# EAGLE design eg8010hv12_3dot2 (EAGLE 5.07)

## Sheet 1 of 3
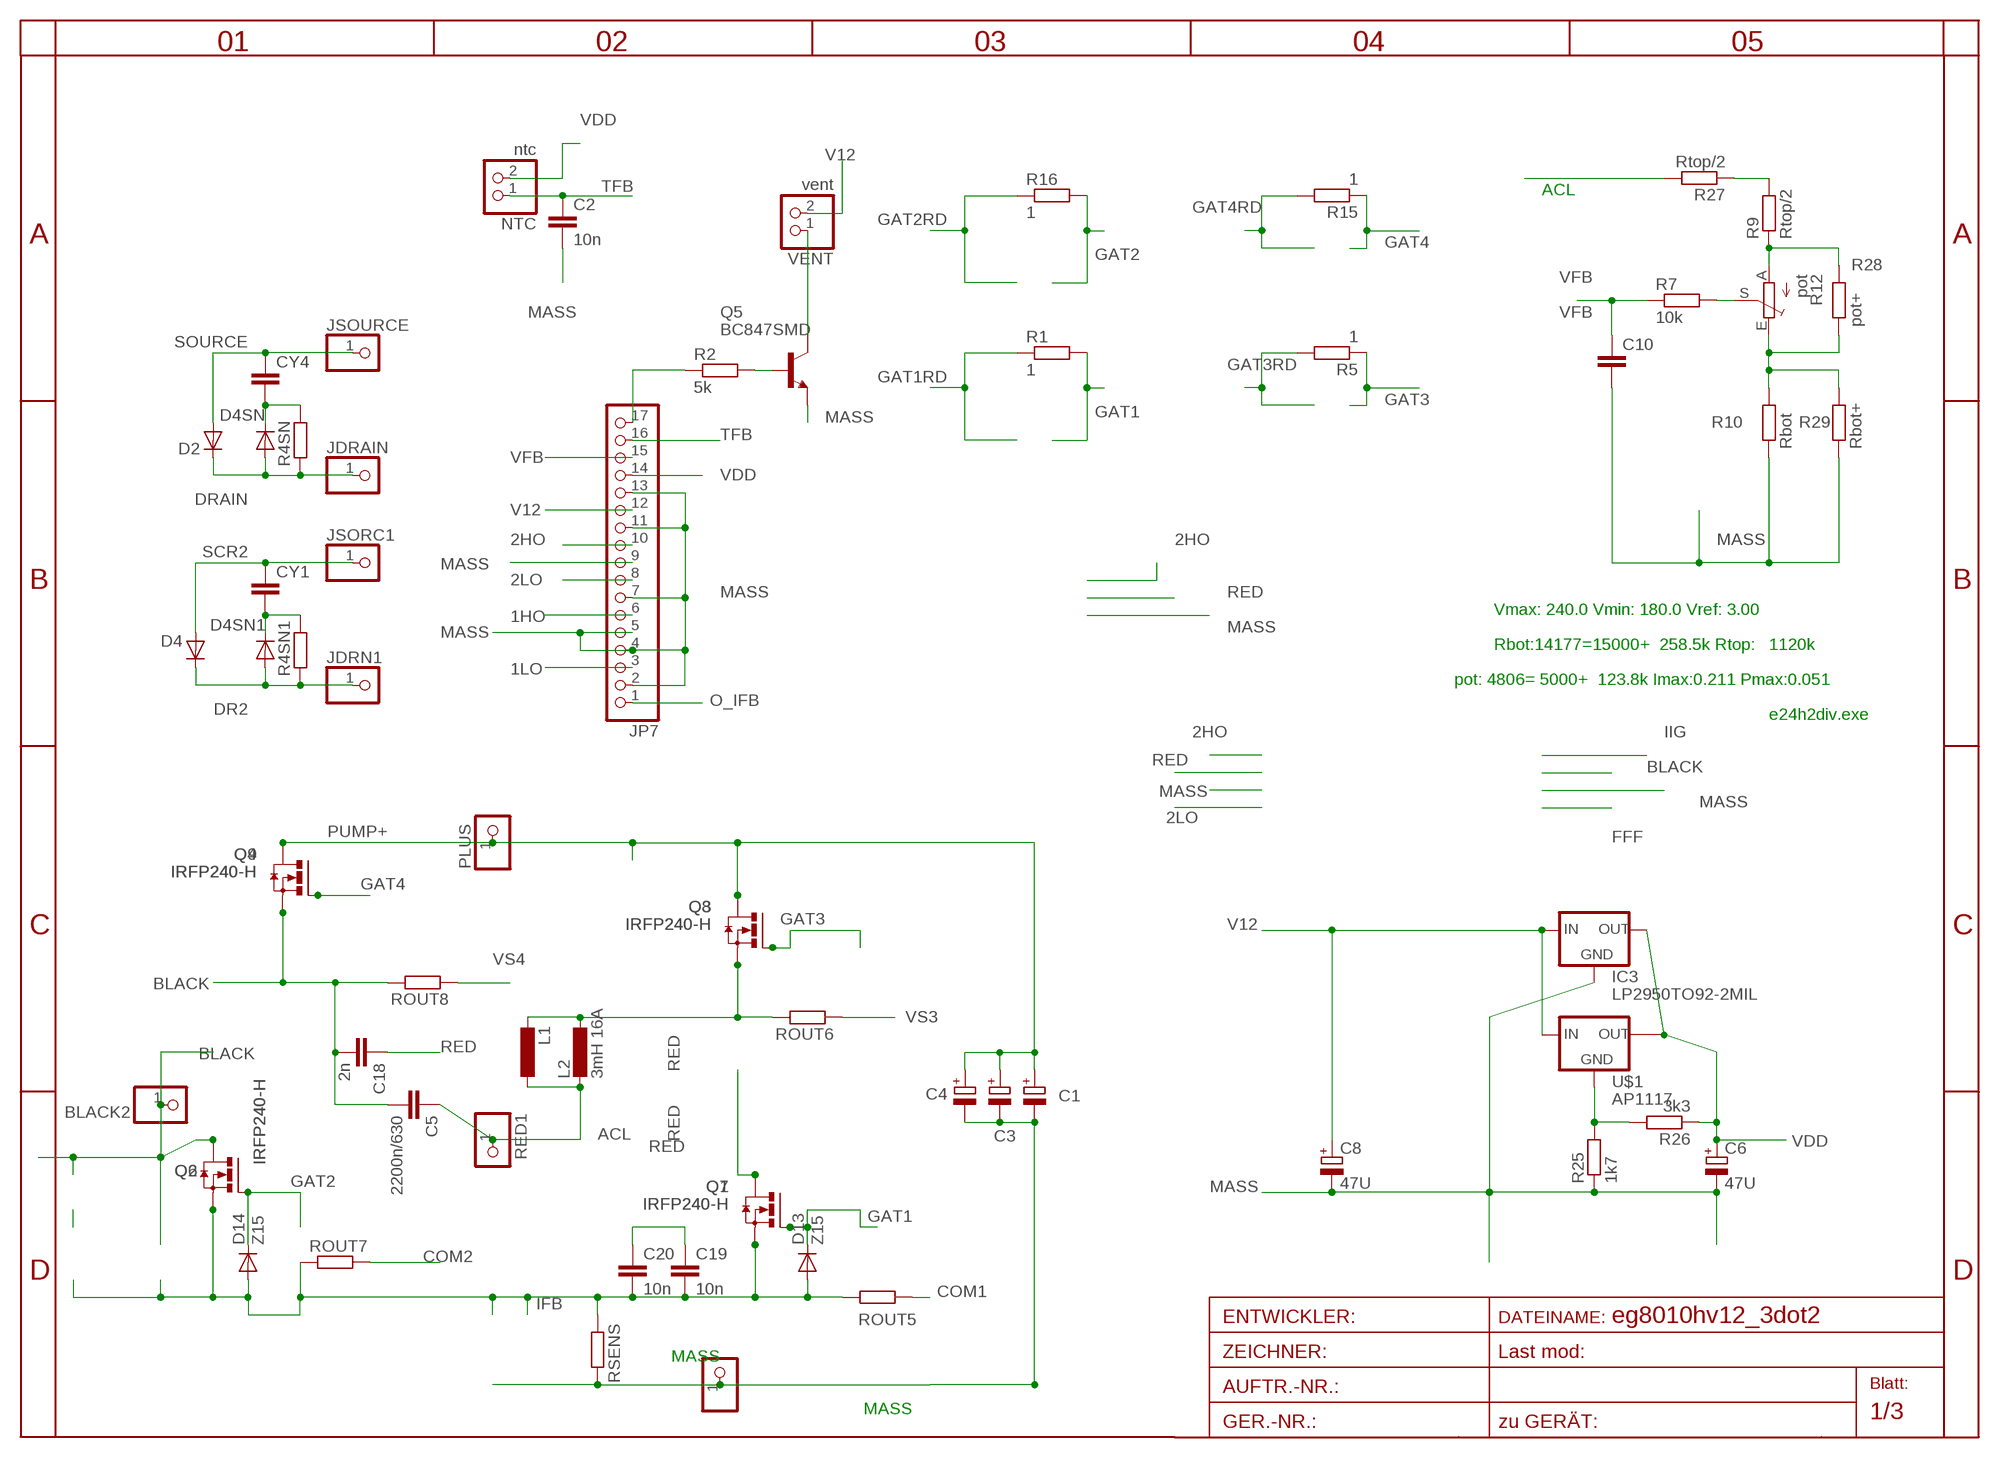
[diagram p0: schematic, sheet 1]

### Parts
BLACK2  PINHD-1X12MM3  [1X2MM3]
C1  CPOL-EUE5-13  [E5-13]
C2  10n  C-EUC0805  [C0805]
C3  CPOL-EUE5-13  [E5-13]
C4  CPOL-EUE5-13  [E5-13]
C5  2200n/630  C-EU275-173X316  [C275-173X316]
C6  47U  CPOL-EUSMCA  [SMC_A]
C8  47U  CPOL-EUSMCA  [SMC_A]
C10  C-EUC0805  [C0805]
C18  2n  C-EU050-024X044  [C050-024X044]
C19  10n  C-EU050-024X044  [C050-024X044]
C20  10n  C-EU050-024X044  [C050-024X044]
CY1  CXXC10B5  [XC10B5]
CY4  CXXC10B5  [XC10B5]
D2  DIODE-SMC  [SMC]
D4  DIODE-SMC  [SMC]
D4SN  DIODE-P1-10  [P1-10]
D4SN1  DIODE-P1-10  [P1-10]
D13  Z15  DIODE-MINIMELF  [MINIMELF]
D14  Z15  DIODE-MINIMELF  [MINIMELF]
IC3  LP2950TO92-2MIL  [TO92-2MIL]
JDRAIN  PINHD-1X11MM0  [1X1MM0]
JDRN1  PINHD-1X11MM0  [1X1MM0]
JP7  PINHD-1X17  [1X17]
JSORC1  PINHD-1X11MM0  [1X1MM0]
JSOURCE  PINHD-1X11MM0  [1X1MM0]
L1  L-EU4.13  [0204/13]
L2  3mH 16A  L-EURNG  [RING]
MINUS  PINHD-1X12MM3  [1X2MM3]
NTC  ntc  PINHD-1X2STR  [1X02]
PLUS  PINHD-1X12MM3  [1X2MM3]
Q1  IRFP240-H  [TO247BH]
Q2  IRFP240-H  [TO247BH]
Q3  IRFP240-H  [TO247BH]
Q4  IRFP240-H  [TO247BH]
Q5  BC847SMD  [SOT23]
Q6  IRFP240-H  [TO247BH]
Q7  IRFP240-H  [TO247BH]
Q8  IRFP240-H  [TO247BH]
Q9  IRFP240-H  [TO247BH]
R1  1  R-EU_R2512  [R2512]
R2  5k  R-EU_R0805  [R0805]
R4SN  R-EU_0207/10  [0207/10]
R4SN1  R-EU_0207/10  [0207/10]
R5  1  R-EU_R2512  [R2512]
R7  10k  R-EU_R0805  [R0805]
R9  Rtop/2  R-EU_R1206  [R1206]
R10  Rbot  R-EU_R0805  [R0805]
R12  pot  TRIM_EU-B64Y  [B64Y]
R15  1  R-EU_R2512  [R2512]
R16  1  R-EU_R2512  [R2512]
R25  1k7  R-EU_R0805  [R0805]
R26  3k3  R-EU_R0805  [R0805]
R27  Rtop/2  R-EU_R1206  [R1206]
R28  pot+  R-EU_R1206  [R1206]
R29  Rbot+  R-EU_R0805  [R0805]
RED1  PINHD-1X12MM3  [1X2MM3]
ROUT5  R-EU_R2512  [R2512]
ROUT6  R-EU_R2512  [R2512]
ROUT7  R-EU_R2512  [R2512]
ROUT8  R-EU_R2512  [R2512]
RSENS  R-EU_WIRE  [WIRE]
U$1  AP1117  [SOT223]
VENT  vent  PINHD-1X2STR  [1X02]

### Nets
1HO: JP7.6 ; also sheet 3
1LO: JP7.3 ; also sheet 3
2HO: JP7.10 ; also sheet 3
2LO: JP7.8 ; also sheet 3
ACL: C5.1 L1.1 L2.2 R27.2 RED1.1
BLACK: BLACK2.1 C5.2 C18.2 Q2.D Q4.S Q6.D Q9.S ROUT8.2
COM1: ROUT5.1 ; also sheet 3
COM2: ROUT7.2 ; also sheet 3
DR2: D4.C D4SN1.A JDRN1.1 R4SN1.1
DRAIN: D2.C D4SN.A JDRAIN.1 R4SN.1
GAT1: D13.C Q1.G Q7.G R1.2
GAT1RD: R1.1 ; also sheet 3
GAT2: D14.C Q2.G Q6.G R16.2
GAT2RD: R16.1 ; also sheet 3
GAT3: Q3.G Q8.G R5.1
GAT3RD: R5.2 ; also sheet 3
GAT4: Q4.G Q9.G R15.1
GAT4RD: R15.2 ; also sheet 3
IFB: C19.2 C20.2 D13.A D14.A Q1.S Q2.S Q6.S Q7.S ROUT5.2 ROUT7.1 RSENS.1 ; also sheet 3
MASS: C1.- C2.2 C3.- C4.- C6.- C8.- C10.2 IC3.2(GND) JP7.2 JP7.4 JP7.5 JP7.7 JP7.9 JP7.11 JP7.13 MINUS.1 Q5.2(E) R10.1 R25.1 R29.1 RSENS.2 ; also sheet 2,3
N$1: Q5.3(C) VENT.1
N$2: Q5.1(B) R2.2
N$3: JP7.17 R2.1
N$17: R25.2 R26.2 U$1.1(GND)
N$23: R9.2 R27.1
N$29: R10.2 R12.E R28.1 R29.2
N$30: R9.1 R12.A R28.2
N$31: R7.2 R12.S
O_IFB: JP7.1 ; also sheet 3
PUMP+: C1.+ C3.+ C4.+ C19.1 C20.1 PLUS.1 Q3.D Q4.D Q8.D Q9.D ; also sheet 2
RED: C18.1 L1.2 L2.1 Q1.D Q3.S Q7.D Q8.S ROUT6.2
SCR2: CY1.1 D4.A JSORC1.1
SNUB1: CY1.2 D4SN1.C R4SN1.2
SNUB2: CY4.2 D4SN.C R4SN.2
SOURCE: CY4.1 D2.A JSOURCE.1
TFB: C2.1 JP7.16 NTC.1
V12: C8.+ IC3.3(IN) JP7.12 U$1.3(IN) VENT.2 ; also sheet 2,3
VDD: C6.+ IC3.1(OUT) JP7.14 NTC.2 R26.1 U$1.4(TAB)
VFB: C10.1 JP7.15 R7.1
VS3: ROUT6.1 ; also sheet 3
VS4: ROUT8.1 ; also sheet 3
Unconnected: U$1.2(OUT)

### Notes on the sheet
- Vmax: 240.0 Vmin: 180.0 Vref: 3.00
- Rbot:14177=15000+  258.5k Rtop:   1120k
- pot: 4806= 5000+  123.8k Imax:0.211 Pmax:0.051
- e24h2div.exe

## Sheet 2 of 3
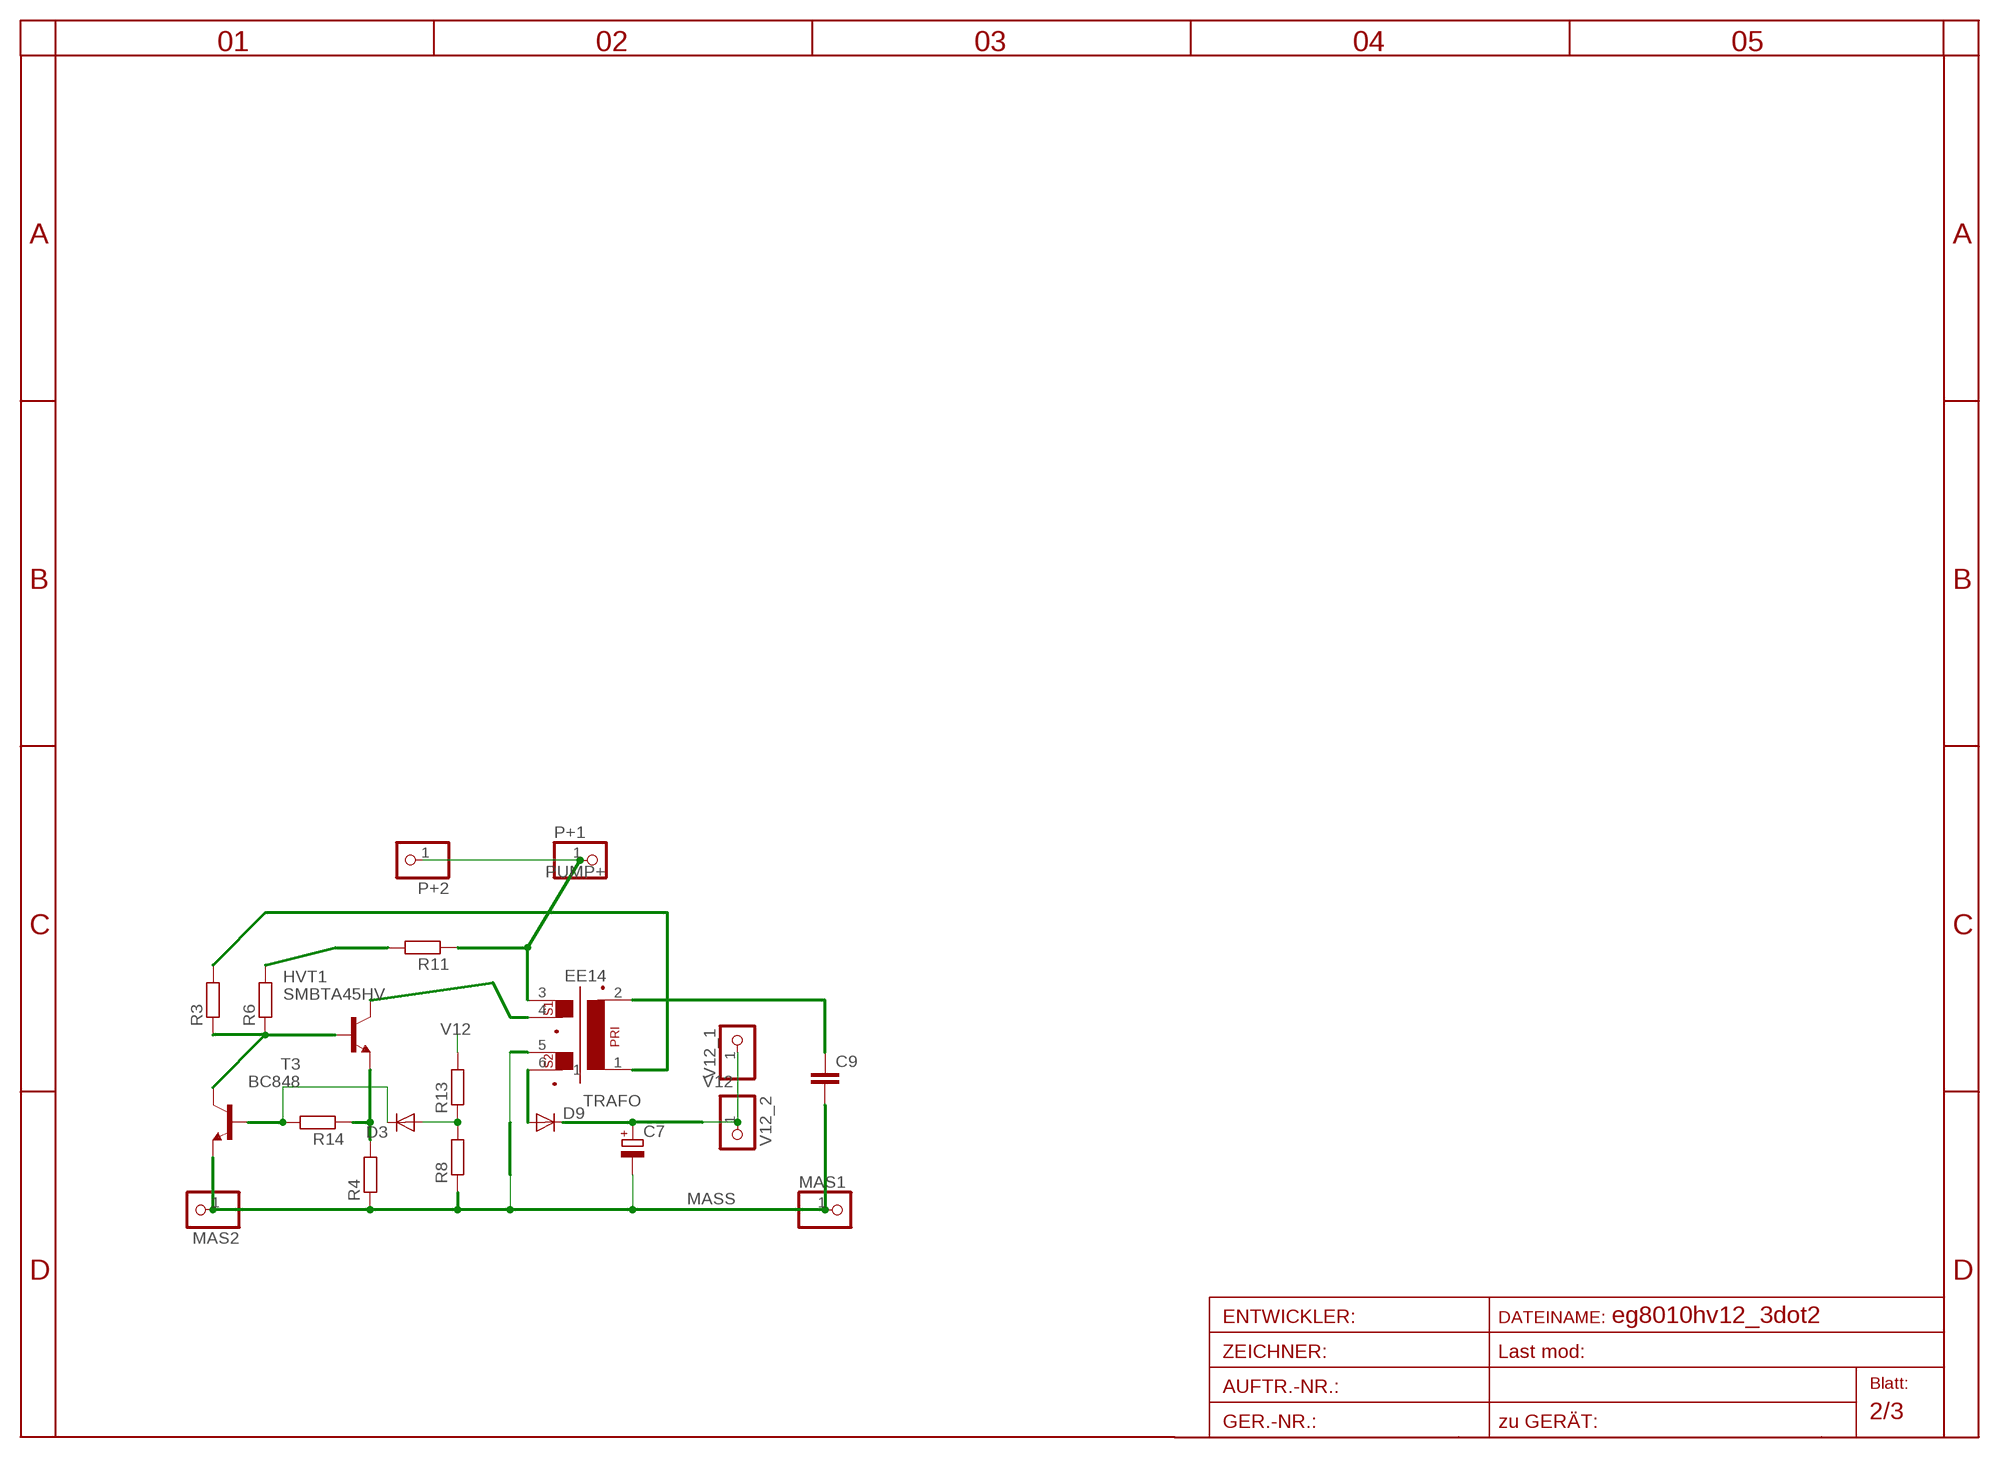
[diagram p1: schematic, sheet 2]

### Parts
C7  CPOL-EUSMCA  [SMC_A]
C9  C-EUC0805  [C0805]
D3  DIODE-MINIMELF  [MINIMELF]
D9  DIODE-SMA-DO214  [SMA-DO214AC]
HVT1  SMBTA45HV  [SOT23HV]
MAS1  PINHD-1X11X0.4  [1X01]
MAS2  PINHD-1X11X0.4  [1X01]
P+1  PINHD-1X11X0.4  [1X01]
P+2  PINHD-1X11X0.4  [1X01]
R3  R-EU_R0805  [R0805]
R4  R-EU_R0805  [R0805]
R6  R-EU_R1206  [R1206]
R8  R-EU_R0805  [R0805]
R11  R-EU_R1206  [R1206]
R13  R-EU_R0805  [R0805]
R14  R-EU_R0805  [R0805]
T3  BC848  [SOT23]
TRAFO  EE14  [EE14]
V12_1  PINHD-1X11X0.4  [1X01]
V12_2  PINHD-1X11X0.4  [1X01]

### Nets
A: D9.A TRAFO.6
B1C2: HVT1.1(B) R3.1 R6.1 T3.C
BT1: D3.C R14.2 T3.B
C1: HVT1.3(C) TRAFO.4
EB: HVT1.2(E) R4.2 R14.1
MASS: C7.- C9.2 MAS1.1 MAS2.1 R4.1 R8.1 T3.E TRAFO.5 ; also sheet 1,3
N$6: R3.2 TRAFO.1
N$7: C9.1 TRAFO.2
N$8: R6.2 R11.2
N$10: D3.A R8.2 R13.1
PUMP+: P+1.1 P+2.1 R11.1 TRAFO.3 ; also sheet 1
V12: C7.+ D9.K(C) R13.2 V12_1.1 V12_2.1 ; also sheet 1,3

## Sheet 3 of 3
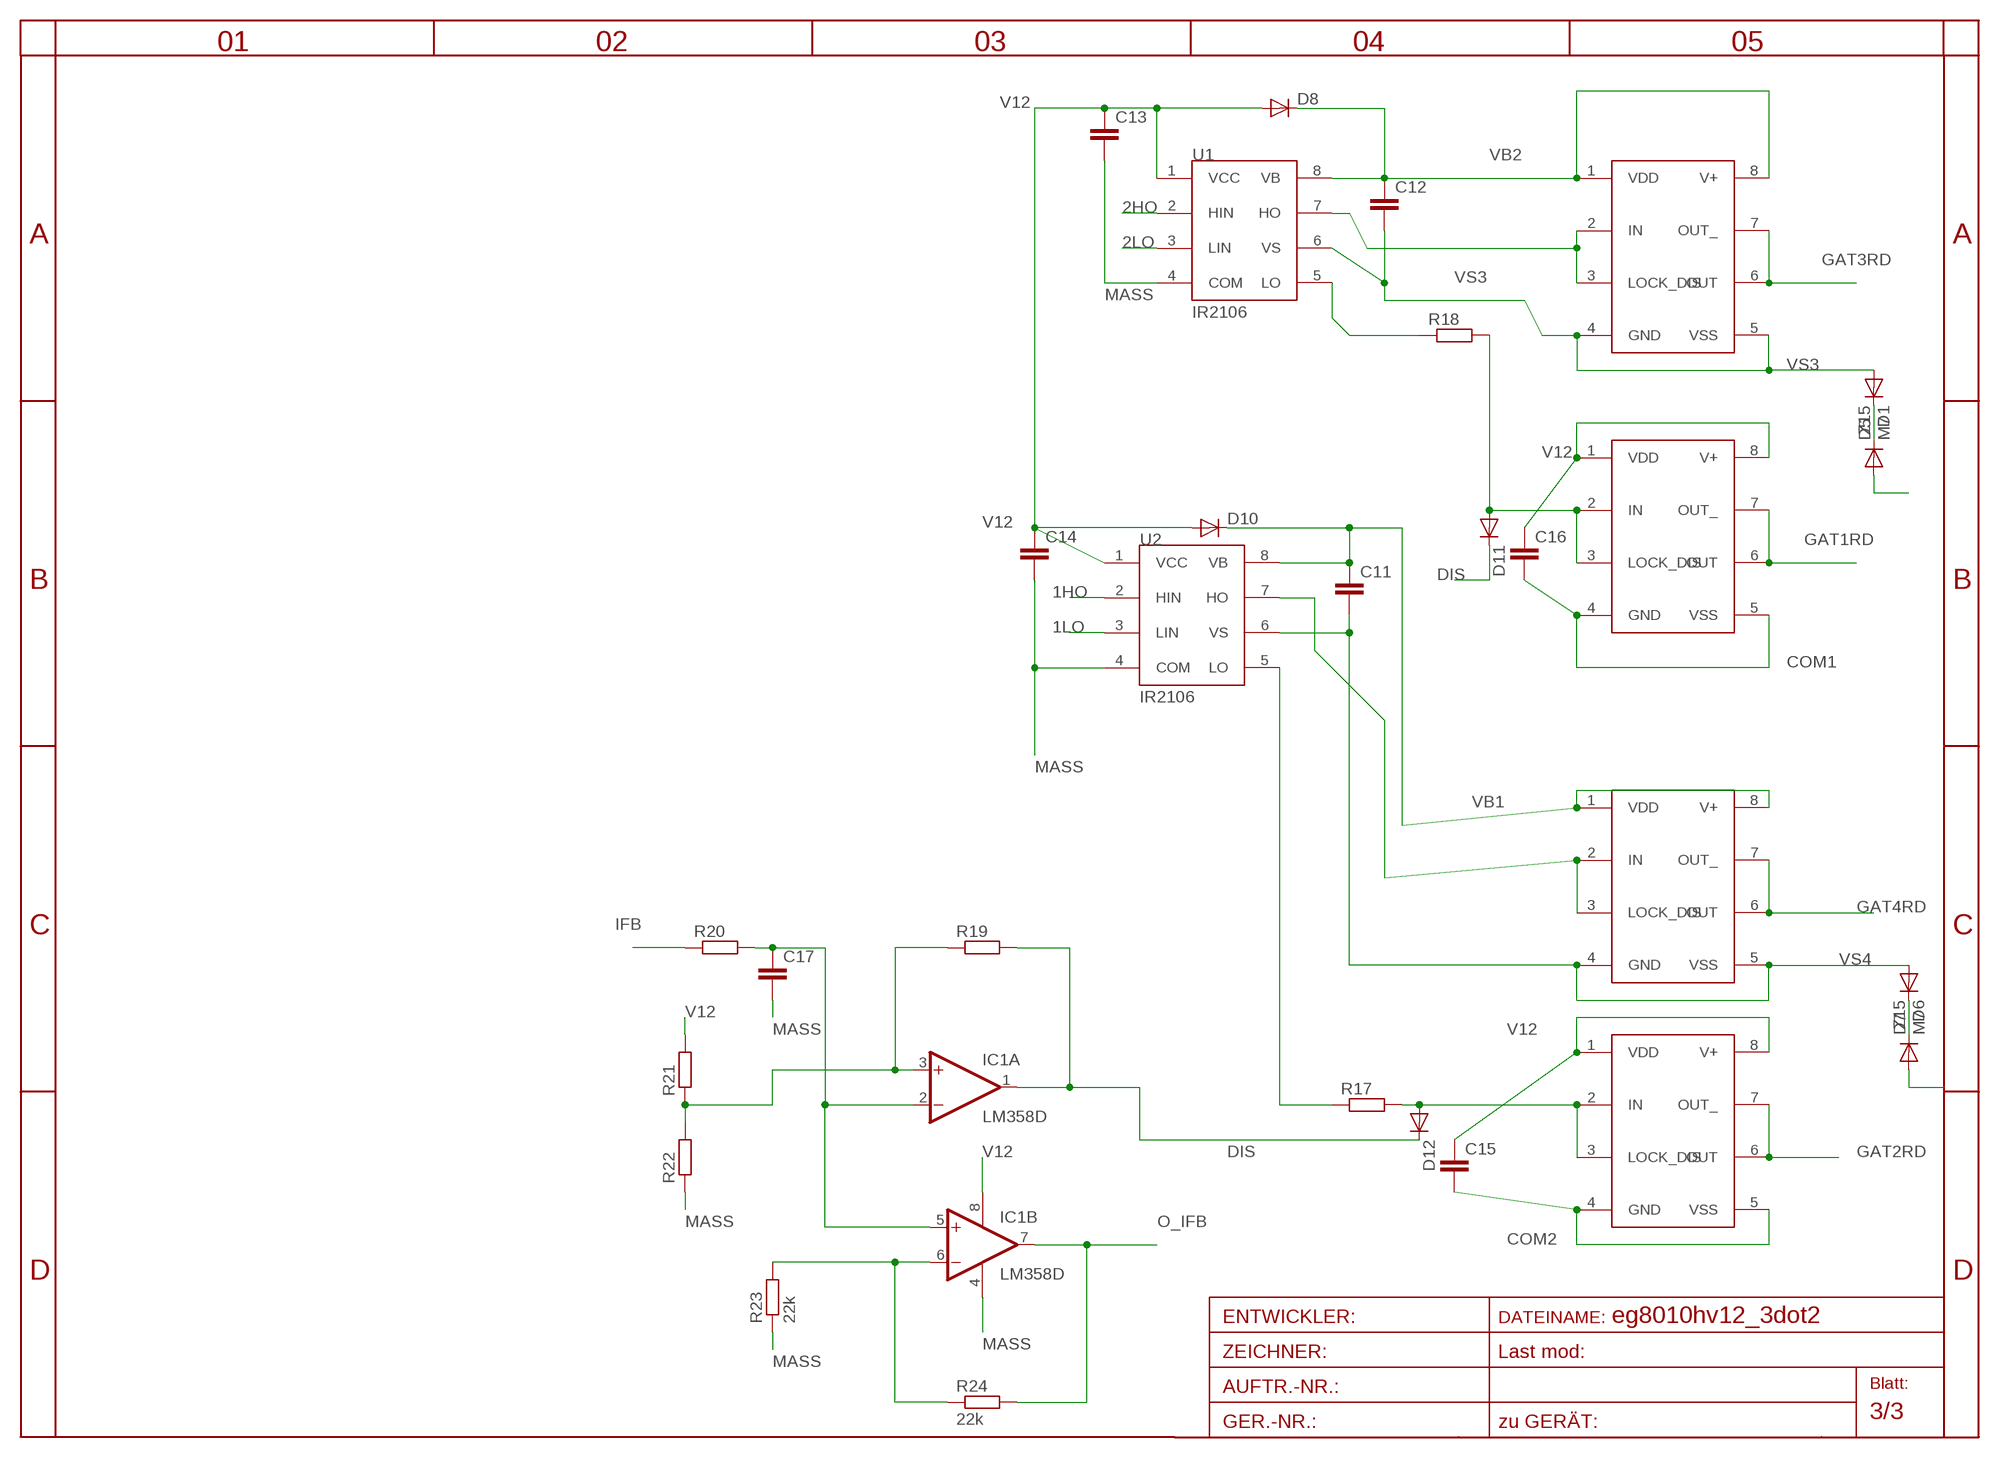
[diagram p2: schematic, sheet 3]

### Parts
1HDRV  TC4432X  [SO-08]
1LODRV  TC4432X  [SO-08]
2HDRV  TC4432X  [SO-08]
2LODRV  TC4432X  [SO-08]
C11  C-EUC058MLCC  [C058-020X040]
C12  C-EUC058MLCC  [C058-020X040]
C13  C-EUC1206  [C1206]
C14  C-EUC0805  [C0805]
C15  C-EUC1206  [C1206]
C16  C-EUC1206  [C1206]
C17  C-EUC1206  [C1206]
D1  Z15  DIODE-MINIMELF  [MINIMELF]
D5  M7  DIODE-SMA-DO214  [SMA-DO214AC]
D6  Z15  DIODE-MINIMELF  [MINIMELF]
D7  M7  DIODE-SMA-DO214  [SMA-DO214AC]
D8  DIODE-SMA-DO214  [SMA-DO214AC]
D10  DIODE-SMA-DO214  [SMA-DO214AC]
D11  DIODE-MINIMELF  [MINIMELF]
D12  DIODE-MINIMELF  [MINIMELF]
IC1  LM358D  [SO08]
R17  R-EU_0207-17  [0207/17]
R18  R-EU_0204/5  [0204/5]
R19  R-EU_R1206  [R1206]
R20  R-EU_R0805  [R0805]
R21  R-EU_R0805  [R0805]
R22  R-EU_R0805  [R0805]
R23  22k  R-EU_R0805  [R0805]
R24  22k  R-EU_R0805  [R0805]
U1  IR2106  [SO8-5]
U2  IR2106  [SO8-5]

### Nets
1HO: U2.2(HIN) ; also sheet 1
1LO: U2.3(LIN) ; also sheet 1
2HO: U1.2(HIN) ; also sheet 1
2LO: U1.3(LIN) ; also sheet 1
COM1: 2LODRV.4(GND) 2LODRV.5(VSS) C16.2 ; also sheet 1
COM2: 1LODRV.4(GND) 1LODRV.5(VSS) C15.2 ; also sheet 1
DIS: D11.C D12.C IC1.1(A:OUT) R19.2
GAT1RD: 2LODRV.6(OUT) 2LODRV.7(OUT_) ; also sheet 1
GAT2RD: 1LODRV.6(OUT) 1LODRV.7(OUT_) ; also sheet 1
GAT3RD: 2HDRV.6(OUT) 2HDRV.7(OUT_) ; also sheet 1
GAT4RD: 1HDRV.6(OUT) 1HDRV.7(OUT_) ; also sheet 1
IFB: R20.1 ; also sheet 1
MASS: C13.2 C14.2 C17.2 D5.A D7.A IC1.4(P:V-) R22.1 R23.1 U1.4(COM) U2.4(COM) ; also sheet 1,2
N$4: R18.1 U1.5(LO)
N$5: 1LODRV.2(IN) 1LODRV.3(LOCK_DIS) D12.A R17.2
N$9: IC1.3(A:+IN) R19.1 R21.1 R22.2
N$11: R17.1 U2.5(LO)
N$12: 2HDRV.2(IN) 2HDRV.3(LOCK_DIS) U1.7(HO)
N$13: 1HDRV.2(IN) 1HDRV.3(LOCK_DIS) U2.7(HO)
N$15: C17.1 IC1.2(A:-IN) IC1.5(B:+IN) R20.2
N$16: 2LODRV.2(IN) 2LODRV.3(LOCK_DIS) D11.A R18.2
N$18: IC1.6(B:-IN) R23.2 R24.1
N$20: D1.C D5.K(C)
N$24: D6.C D7.K(C)
O_IFB: IC1.7(B:OUT) R24.2 ; also sheet 1
V12: 1LODRV.1(VDD) 1LODRV.8(V+) 2LODRV.1(VDD) 2LODRV.8(V+) C13.1 C14.1 C15.1 C16.1 D8.A D10.A IC1.8(P:V+) R21.2 U1.1(VCC) U2.1(VCC) ; also sheet 1,2
VB1: 1HDRV.1(VDD) 1HDRV.8(V+) C11.1 D10.K(C) U2.8(VB)
VB2: 2HDRV.1(VDD) 2HDRV.8(V+) C12.1 D8.K(C) U1.8(VB)
VS3: 2HDRV.4(GND) 2HDRV.5(VSS) C12.2 D1.A U1.6(VS) ; also sheet 1
VS4: 1HDRV.4(GND) 1HDRV.5(VSS) C11.2 D6.A U2.6(VS) ; also sheet 1

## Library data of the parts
1HDRV 1LODRV 2HDRV 2LODRV = microchip:TC4432
BLACK2 JDRAIN JDRN1 JSORC1 JSOURCE MAS1 MAS2 MINUS P+1 P+2 PLUS RED1 V12_1 V12_2 = pinhead:PINHD-1X1: PIN HEADER
C1 C3 C4 C6-C8 = rcl:CPOL-EU: POLARIZED CAPACITOR, European symbol
C2 C5 C9-C20 = rcl:C-EU: CAPACITOR, European symbol
CY1 CY4 = rcl:CX: X CAPACITOR
D1-D4 D4SN D4SN1 D5-D14 = diode:DIODE-: DIODE
HVT1 = transistor-npn:SMBTA45
IC1 = linear:LM358: OP AMP also LM158; LM258; LM2904 Source: http://cache.national.com/ds/LM/LM158.pdf
IC3 = v-reg:LP2950?*: Source: http://cache.national.com/ds/LP/LP2950.pdf
JP7 = pinhead:PINHD-1X17: PIN HEADER
L1 L2 = rcl:L-EU: INDUCTOR, European symbol
NTC VENT = pinhead:PINHD-1X2: PIN HEADER
Q1-Q4 Q6-Q9 = transistor-power:IRFP240: HEXFET Power MosFet Source: http://www.irf.com/
Q5 = transistor-npn:BC847*: NPN Transistor
R1-R4 R4SN R4SN1 R5 R6 R8 R11 R13-R24 ROUT5-ROUT8 RSENS = rcl:R-EU_: RESISTOR, European symbol
R7 R9 R10 R25-R29 = rcl-2:R-EU_: RESISTOR, European symbol
R12 = pot:TRIM_EU-: POTENTIOMETER
T3 = transistor:BC848: NPN TRANSISTOR
TRAFO = trafo:EE14
U1 U2 = irf-2:IR2106
U$1 = v-reg:AP1117

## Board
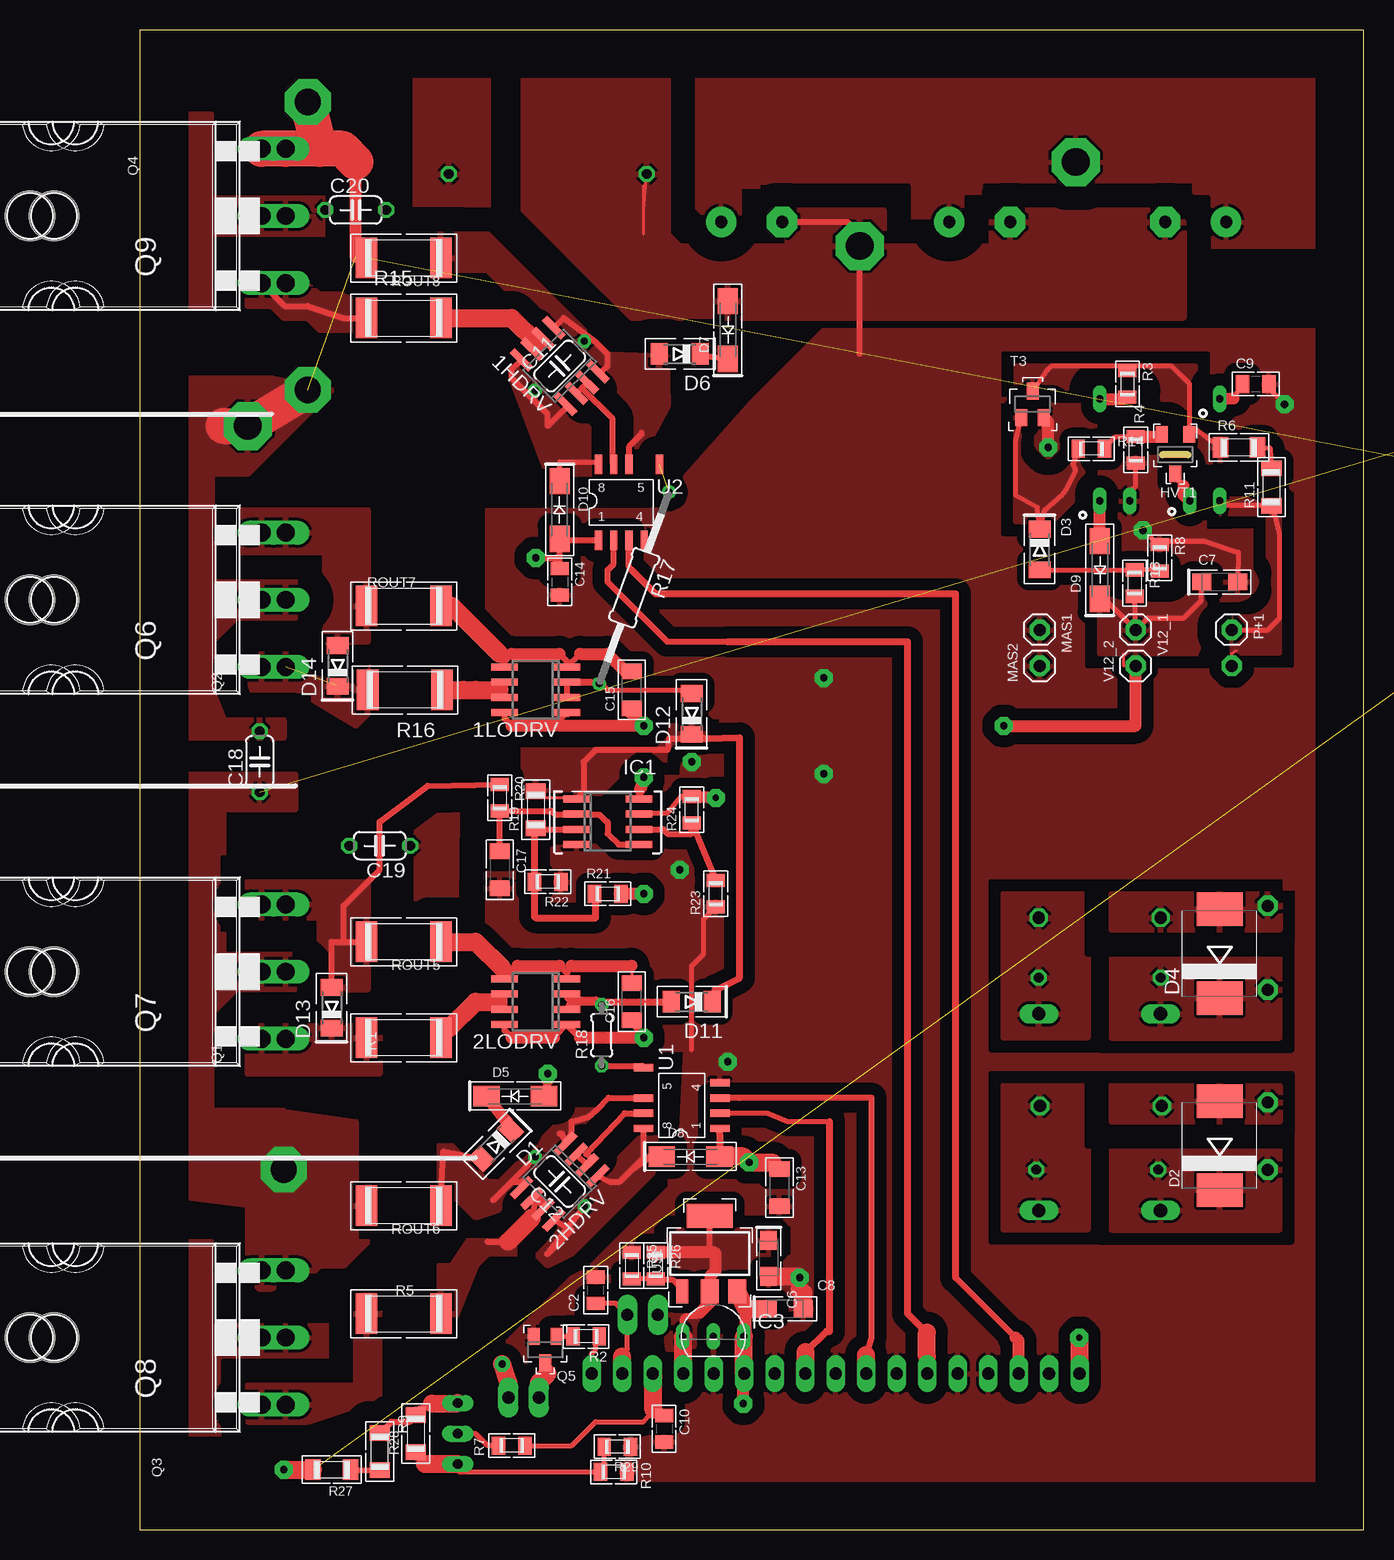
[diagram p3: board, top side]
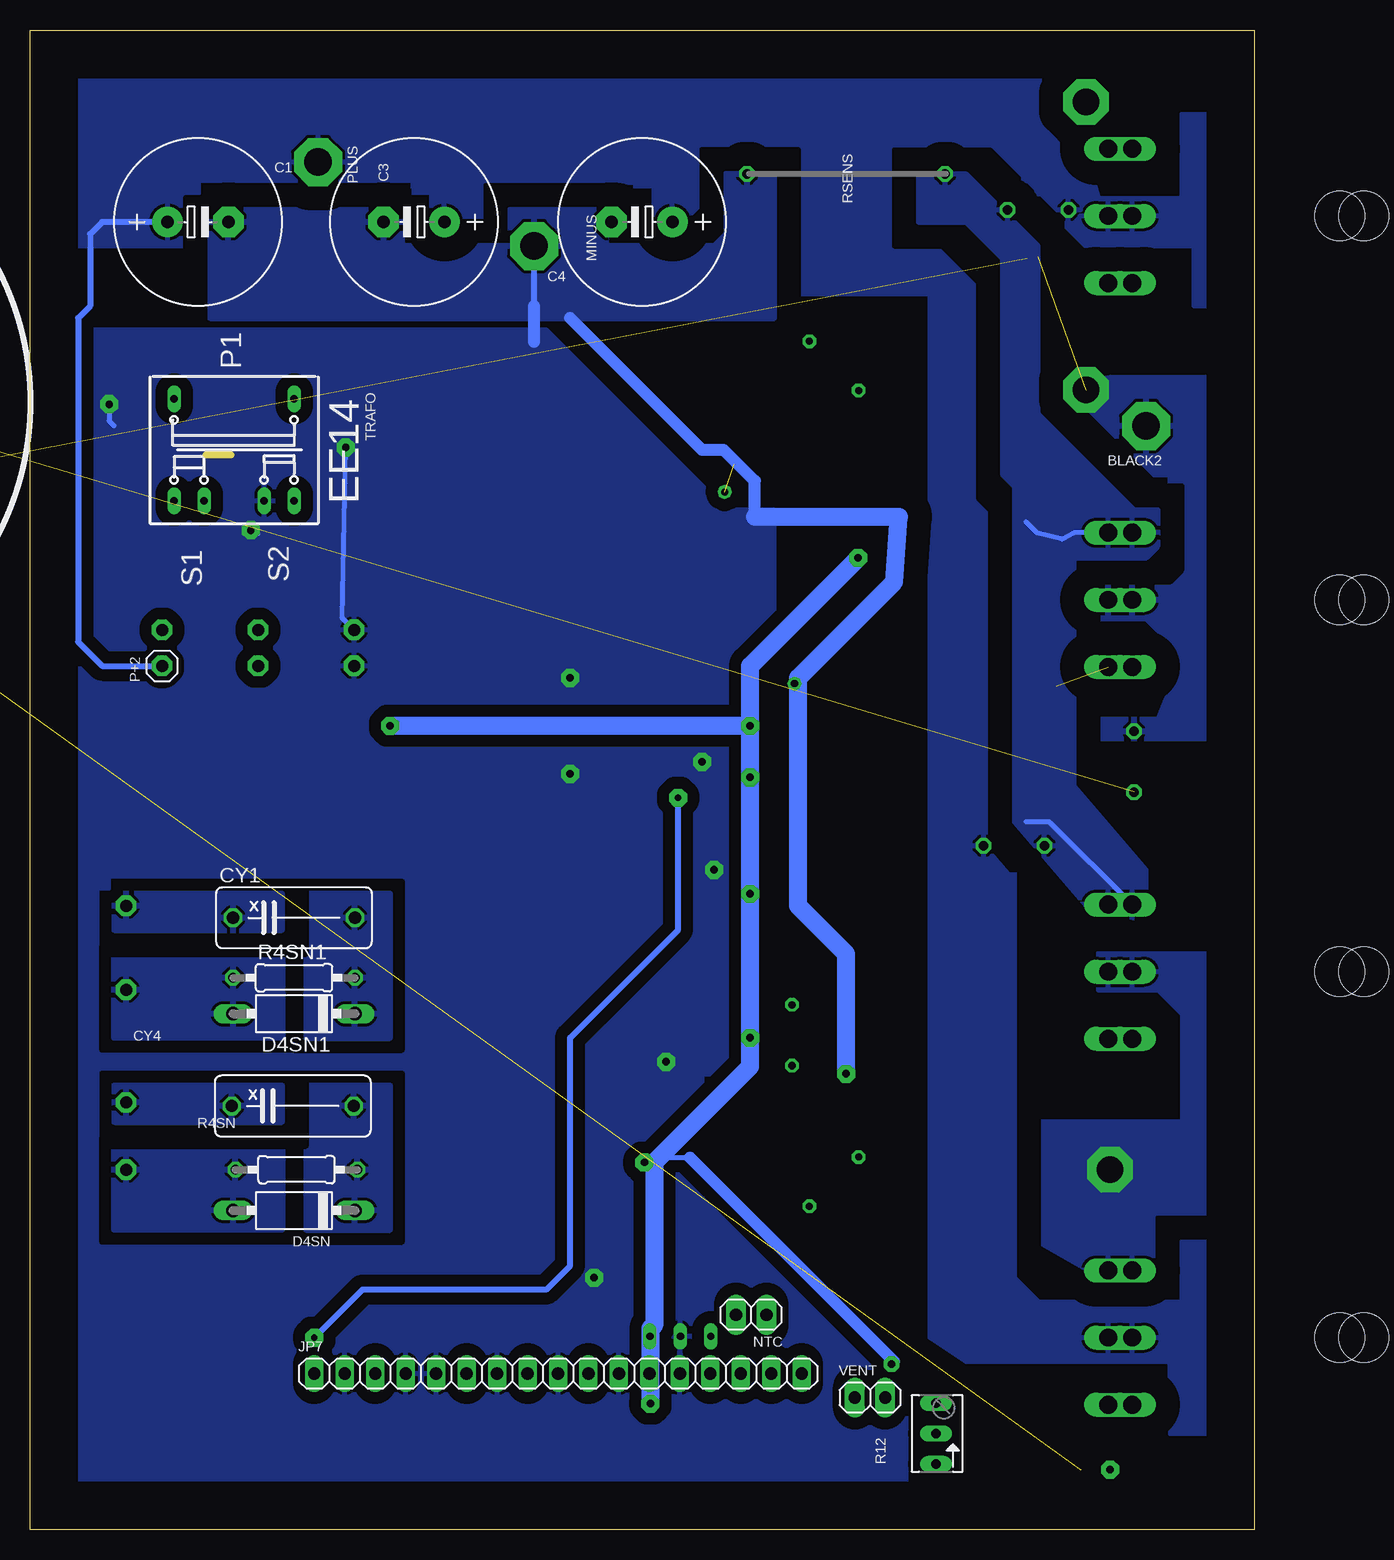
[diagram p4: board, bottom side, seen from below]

Size 102 x 125 mm. Coordinates in mm from the lower left corner, seen from the top.
Outline: 0,0 102,0 102,125 0,125 0,0
Copper layers (1*16): Top 0.035mm / dielectric 1.5mm / Bottom 0.035mm
Design rules "default *": minimum track width 10mil, minimum drill 20mil, track to track 8mil, track to pad 8mil, pad to pad 8mil, via to via 8mil, smd to smd 8mil, copper to edge 4mm, drill to drill 8mil, minimum pad ring 10mil, minimum via ring 8mil, stop-mask expansion 4mil, vias tented up to drill 0mil, thermal gap 10mil

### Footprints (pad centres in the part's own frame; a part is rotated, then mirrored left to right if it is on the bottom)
SO-08 = smd 0.6 x 2.2: 1 -1.905,-2.6; 2 -0.635,-2.6; 3 0.635,-2.6; 4 1.905,-2.6; 5 1.905,2.6; 6 0.635,2.6; 7 -0.635,2.6; 8 -1.905,2.6
1X2MM3 = drill 2.3 pad 4 octagon: 1 0,0
E5-13 = drill 1.016 pad 2.54 round: + -2.54,0 | drill 1.016 pad 2.54 octagon: - 2.54,0
C0805 = smd 1.1 x 1.5: 1 -1.1,0; 2 1.1,0
C275-173X316 = drill 1.194 octagon: 1 -13.716,0; 2 13.716,0
SMC_A = smd 1.6 x 1.4: + -1.5,0; - 1.5,0
C058-020X040 = drill 0.6 octagon: 1 -2.9,0; 2 2.9,0
C1206 = smd 1.3 x 1.7: 1 -1.55,0; 2 1.55,0
C050-024X044 = drill 0.813 octagon: 1 -2.54,0; 2 2.54,0
XC10B5 = drill 1.016 octagon: 1 -5.08,0; 2 5.08,0
MINIMELF = smd 1.4 x 1.8: A 1.7,0; C -1.7,0
SMC = smd 2.8 x 3.8: A 3.7,0; C -3.7,0
P1-10 = drill 1.118 long: A 5.08,0; C -5.08,0
SMA-DO214AC = smd 2.2 x 1.7: A 2.4,0; K -2.4,0
SOT23HV = smd 1 x 1.4: 1 -1.15,-1.7; 2 1.15,-1.7; 3 0,1.6
SO08 = smd 0.6 x 2.2: 1 -1.905,-2.6; 2 -0.635,-2.6; 3 0.635,-2.6; 4 1.905,-2.6; 5 1.905,2.6; 6 0.635,2.6; 7 -0.635,2.6; 8 -1.905,2.6
TO92-2MIL = drill 0.6 pad 0.813 long: 1 -2.54,0; 2 0,0; 3 2.54,0
1X1MM0 = drill 1 pad 1.676 octagon: 1 0,0
1X17 = drill 1.016 long: 1 -20.32,0; 2 -17.78,0; 3 -15.24,0; 4 -12.7,0; 5 -10.16,0; 6 -7.62,0; 7 -5.08,0; 8 -2.54,0; 9 0,0; 10 2.54,0; 11 5.08,0; 12 7.62,0; 13 10.16,0; 14 12.7,0; 15 15.24,0; 16 17.78,0; 17 20.32,0
0204/13 = drill 0.813 octagon: 1 -6.872,0; 2 6.872,0
RING = drill 3 pad 4 round: 1 -3.15,0; 2 3.15,0
1X01 = drill 1 pad 1.676 octagon: 1 0,0
1X02 = drill 1.016 pad 1.676 long: 1 -1.27,0; 2 1.27,0
TO247BH = drill 1.499 long: D 0,-10.16; G -5.588,-10.16; S 5.588,-10.16 | hole 4.115: 0,9.144
SOT23 = smd 1 x 1.4: 1 -0.95,-1.1; 2 0.95,-1.1; 3 0,1.1
R2512 = smd 1.8 x 3.4: 1 -3.1,0; 2 3.1,0
R0805 = smd 1.1 x 1.5: 1 -1.1,0; 2 1.1,0
0207/10 = drill 0.813 octagon: 1 -5.08,0; 2 5.08,0
R1206 = smd 1.3 x 1.7: 1 -1.55,0; 2 1.55,0
B64Y = drill 0.813 long: A 2.54,0; E -2.54,0; S 0,0
0207/17 = drill 0.6 octagon: 1 -8.5,0; 2 8.5,0
0204/5 = drill 0.6 octagon: 1 -2.54,0; 2 2.54,0
WIRE = drill 0.813 octagon: 1 -8.25,0; 2 8.25,0
SOT23' = smd 1 x 1.4: B -0.95,-1.1; C 0,1.1; E 0.95,-1.1
EE14 = drill 0.6 pad 1 long: 1 4.25,-5; 2 4.25,5; 3 -4.25,5 | drill 0.6 pad 1.016 long: 4 -4.25,2.5; 5 -4.25,-2.5; 6 -4.25,-5
SO8-5 = smd 0.61 x 1.626: 1 -1.27,-2.54; 2 0,-2.54; 3 1.27,-2.54; 4 2.54,-2.54; 5 3.81,3.81; 6 1.27,3.81; 7 0,3.81; 8 -1.27,3.81
SOT223 = smd 1 x 2: 1 -2.3,-3.15 | smd 1.5 x 2: 2 0,-3.15; 3 2.3,-3.15 | smd 3.8 x 2: 4 0,3.15

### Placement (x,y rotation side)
1HDRV  35,97 45 top
1LODRV  33,70 90 top
2HDRV  35,29 135 top
2LODRV  33,44 90 top
BLACK2  9,92 180 bottom
C1  88,109 0 bottom
C2  38,19.95 90 top
C3  70,109 180 bottom
C4  51,109 180 bottom
C5  not placed on the board
C6  52.4,22.6 270 top
C7  90,79 0 top
C8  53.8,18.4 0 top
C9  93,95.5 0 top
C10  43.7,8.4 270 top
C11  35,97 45 top
C12  35,29 135 top
C13  53.3,28.5 270 top
C14  35,79 270 top
C15  41,70 90 top
C16  41,44 90 top
C17  30,55 270 top
C18  10,64 90 top
C19  20,57 180 top
C20  18,110 0 top
CY1  80,51 0 bottom
CY4  80.1,35.3 0 bottom
D1  29.7,32.1 225 top
D2  90,32 90 top
D3  75,81.7 270 top
D4  90,48 90 top
D4SN  80,26.6 180 bottom
D4SN1  80,43 180 bottom
D5  31.28,36.14 0 top
D6  45,98 180 top
D7  49,100 90 top
D8  45.9,31.1 0 top
D9  80,80 90 top
D10  35,85 270 top
D11  46,44 180 top
D12  46,68 90 top
D13  16,43.5 90 top
D14  16.5,72 90 top
HVT1  86.3,89.6 180 top
IC1  39,59 270 top
IC3  47.8,16.1 0 top
JDRAIN  94,30 270 top
JDRN1  94,45 0 top
JP7  58,13 0 bottom
JSORC1  94,52 0 top
JSOURCE  94,35.6 270 top
L1  not placed on the board
L2  not placed on the board
MAS1  75,75 270 top
MAS2  75,72 90 top
MINUS  60,107 270 bottom
NTC  41.9,17.9 180 bottom
P+1  91,75 270 top
P+2  91,72 90 bottom
PLUS  78,114 270 bottom
Q1  0,46.5 90 top
Q2  0,77.5 90 top
Q3  0,16 90 top
Q4  0,109.5 90 top
Q5  33.8,15 180 top
Q6  2,77.5 90 top
Q7  2,46.5 90 top
Q8  2,16 90 top
Q9  2,109.5 90 top
R1  22,41 180 top
R2  37.2,16.1 180 top
R3  82.3,95.5 270 top
R4  83,90 90 top
R4SN  79.8,30 0 bottom
R4SN1  80,46 0 bottom
R5  22,18 0 top
R6  91.6,90.2 0 top
R7  31,7 180 top
R8  85,81 270 top
R9  20,6.5 270 top
R10  39.5,4.8 180 top
R11  94.3,86.9 90 top
R12  26.5,8 90 bottom
R13  82.9,78.9 270 top
R14  79.3,90.1 180 top
R15  22,101 0 top
R16  22.1,70 180 top
R17  41.2,78.5 250 top
R18  38.5,41.2 90 top
R19  33,60 90 top
R20  30,61 270 top
R21  39,53 0 top
R22  34,54 180 top
R23  48,53 90 top
R24  46,60 90 top
R25  41,22 270 top
R26  43,22 270 top
R27  16,5 180 top
R28  23,8 90 top
R29  39.8,6.9 180 top
RED1  not placed on the board
ROUT5  22,49 180 top
ROUT6  22,27 180 top
ROUT7  22,77 0 top
ROUT8  22,106 180 top
RSENS  34,113 180 bottom
T3  BC848  [SOT23']  74.4,93.8 0 top
TRAFO  85,90 90 bottom
U1  45.8,34.7 90 top
U2  39.5,85 0 top
U$1  47.5,23 0 top
V12_1  83,75 270 top
V12_2  83,72 90 top
VENT  32,11 0 bottom

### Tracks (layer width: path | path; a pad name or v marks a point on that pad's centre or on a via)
1HO
  Top 0.5: 49,74 44,74 39,79 39,80 39.5,80.5 U2.2
  Top 0.6: 65.6,16.4 64,18 64,74 49,74
  Top 1: JP7.6 65.6,14.4
  Top 1.5: 65.6,14.4 65.6,16.4
1LO
  Top 0.5: 73,16 68,21 | U2.3 40.77,80.23 41,80
  Top 0.6: 68,21 68,78 43,78 41,80
  Top 1: JP7.3 73.24,15.76 73,16
2HO
  Top 0.406: U1.2 52.3,34.7 54,34 57.5,34
  Top 0.6: 57.5,34 57.5,16.5 57.24,16.54 55.5,14.8
  Top 1.5: JP7.10 55.5,14.8
2LO
  Top 0.5: 60.54,14.54 61,16 61,36 50,36 49.97,35.97 U1.3
  Top 1.5: JP7.8 60.54,14.54
A
  Top 1: D9.A TRAFO.6
ACL  (via drill 0.6 pad 1.5)  (4 unrouted)
  Top 1.5: v12,5 R27.2
B1C2
  Top 0.406: R6.1 88.05,91.7 HVT1.1 87.45,95.55 86,97 82.9,97 | 82.7,97 R3.1 82.9,97 | T3.C 75.6,96.6 76,97 82.7,97 | 82.9,97 82.7,97
  pour Top (isolate 2): 88,92 88,97 73,97 73,94 86,94 86,92 89,89 91,89 91,91
BLACK  (via drill 2.2 pad 3.81)  (2 unrouted)
  Top 1: 18,114 18,106.1 ROUT8.2
  Top 3: 15,115.09 16.91,115.09 18,114 | 15,115.09 Q9.S Q4.S | v14,95 BLACK2.1 7,92 | 15,115.09 v14,119
  pour Top (isolate 2): 16,95 9,88 6,88 6,79 13,79 13,76 8,76 6,74 6,70 7,67.5 12,67.5 12,66 3,66 3,96 11,96
  pour Bottom (isolate 2, rank 5): 17,95 10,88 7,88 7,79 14,79 14,76 9,76 7,74 7,70 8,67.5 13,67.5 13,66 4,66 4,96 12,96
BT1
  Top 0.406: T3.B 73,90.75 73,86.2 74.8,85.2 D3.C 75.4,85 76.9,86.3 77.2,86.7 78,88.3 77.8,88.8 R14.2
  pour Top (isolate 1.5, rank 2): 80,90 80,88 76,84 73,84 73,93 75,93 75,92 77,90
C1
  Top 0.406: HVT1.3 86.3,87.7 87,87
  Top 1: 87,87 87,86.25 TRAFO.4
COM1
  Top 0.254: 41,47 C16.2 | 2LODRV.4 36,47
  Top 0.5: 2LODRV.4 35.6,46.4 35,47 | 31.25,46.75 2LODRV.5 | 31.25,46.75 31.5,47 | 30.25,46.75 31.25,46.75
  Top 1: 36,47 41,47 | 31.5,47 35,47
  Top 1.5: ROUT5.1 28,49 30.25,46.75
COM2
  Top 0.5: 31,73 30.4,72.4 1LODRV.5 30,73 | 35,73 36,72 35.69,72 1LODRV.4 36.69,73 | 40.45,71.55 C15.2 | 26,77 25.81,77.19 ROUT7.2
  Top 1: 31,73 35,73 | 40.45,71.55 39,73 36.69,73
  Top 1.5: 30,73 26,77
DIS
  Top 0.254: R19.2 33,61 36,61 IC1.1
  Top 0.5: 48,45 47.9,45 D11.C | 47.1,65.9 44.1,65.9 44,65 38,65 37,64 37,61.51 IC1.1
  Top 0.6: 48,45 50,46 50,66 47.1,65.9 D12.C
  pour Top (isolate 1.27, rank 2): 32,67 47,67 47,63 40,63 38,61 32,61 32,66
DR2
  pour Top (isolate 2, rank 2): 95,48 81,48 81,41 95,41
  pour Bottom (isolate 2, rank 2): 95,48 81,48 81,41 95,41
DRAIN
  pour Top (isolate 2, rank 2): 95,32 81,32 81,25 95,25
  pour Bottom (isolate 2, rank 2): 95,32 81,32 81,25 95,25
EB
  Top 0.406: R14.1 81.3,91.1 R4.2 | 84.95,91.1 HVT1.2
  Top 1: R4.2 84.95,91.1
GAT1
  pour Top (isolate 2): 9,42 20,42 20,38 9,38
GAT1RD
  Top 0.5: 2LODRV.6 2LODRV.7 29.77,44 | R1.1 25.81,41.81
  Top 1.5: 29.77,44 28,44 25.81,41.81
GAT2  (1 unrouted)
  pour Top (isolate 2, rank 2): 8,73 14,73 16,76 19,76 19,68 18,67 13,70 8,70
GAT2RD
  Top 0.5: 1LODRV.7 1LODRV.6 30.4,70.4 30,70
  Top 1.5: 30,70 28,70 27,70 R16.1
GAT3
  pour Top (isolate 2, rank 3): 9,12 9,9 14,9 20,11 20,20 18,20 18,12
GAT3RD
  Top 0.5: 32.7,26 33,27.4 2HDRV.6 33.82,27 34,27 33,27.82 2HDRV.7 | 29,24 30.7,24
  Top 1.5: 30.7,24 32.7,26
  pour Top (isolate 1.5, rank 2): 28,25 35,28 32,23 29,23 28,22 26,17 25,17 25,22 26,22
GAT4
  Top 0.5: Q4.G 12.07,102 14,102 17,101 R15.1
  pour Top (isolate 1.5): 8.9,104.5 12.9,104.5 15,103 18,103 19,102 19,101 18,100 15,100 14,101 12,101 11,102 9,102
GAT4RD
  Top 0.5: 33.16,98.84 1HDRV.7 | 33.16,98.84 1HDRV.6 | 33.16,98.84
  Top 1.5: R15.2 31,101 33.16,98.84
IFB
  Top 0.5: R20.1 29.9,62.1 24,62 20,59 20,55 17,52 17,49 | 17,49 16,49 D13.A | 17,49 ROUT5.2
  Bottom 0.406: Q1.S 17.07,59 19,59 | 19,84 18.08,83.08 16,82.55 14.99,83.09 Q2.S
  pour Bottom (isolate 2): 28,113 28,109 24,109 21,106 21,88 20,87 20,59 14,52 10,51 9,52 9,55 15,62 15,81 9,81 8,82 8,85 10,85 18,93 18,107 24,113
  pour Top (isolate 2, rank 2): 23,121 29,121 29,109 23,109
  pour Top (isolate 2, rank 2): 9,51 9,54 16,54 19,54 19,45 15,45 15,51
  pour Top (isolate 2, rank 2): 8,85 19,85 19,74 14,74 14,81 8,81
MASS  (via drill 0.6 pad 1.5)
  Top 0.254: 42,110 42,112 | C4.- 53,109 | 42,108 42,110 | 42,110 RSENS.2
  Top 0.4: 46,40 46,47 47,48 47,50.9 R23.1
  Top 0.406: C7.- 91.55,81.45 88.7,82.4 85.8,82.4 R8.1 84.9,82.1 v83.6,83.3 | C9.2 94.1,95.1 v95.4,93.8 | TRAFO.5 82.5,86.5 83,87 R4.1
  Top 0.5: C4.- 59,109 60,108 60,98 | D5.A 34,37.4
  Top 1: v75.7,90.2 75.7,92.35 T3.E | 34,37.4 v34,38
  Top 1.5: C6.- 54.9,21.1 v55,21 | C8.- 55.3,19.7 55,20
  Bottom 0.406: v75.7,90.2 76,76 MAS1.1 | v95.4,93.8 95.4,92.4 95,92 | 83,83 v83.6,83.3
  Bottom 0.5: 60,102 MINUS.1
  Bottom 1: 41.6,84.4 41.6,87.4 44.2,90 46,90 57,101 | 60,99 60,102
  Bottom 1.5: v34,38 34,48 38,52 38,71 30,79 29.6,84.4 41.6,84.4
  other vias: 49,39 45,55 57,63 57,71 46,64
  pour Bottom (isolate 2): 96,97 96,73 73,73 73,97
  pour Top (isolate 2, rank 5): 96,97 96,73 73,73 73,97
  pour Bottom (isolate 1, rank 4): 44,85 59,100 105,100 105,4 29,4 29,14 44,28 46,30 46,38 40,38 40,85
  pour Top (isolate 1, rank 4): 51,94 57,100 100,100 100,4 29,4 29,14 45,30 45.5,40 29,40 29,85 43,85
  pour Bottom (isolate 2, rank 2): 40,113 44,113 44,108 45,107 54,107 54,110 62,110 62,107 71,107 71,110 86,110 87,109 87,101 40,101
  pour Top (isolate 2, rank 2): 32,121 44,121 44,108 45,107 54,107 54,110 62,110 62,107 71,107 71,110 86,110 87,109 87,101 41,101 32,110
N$1
  Top 0.406: VENT.1 33.27,12.27 | 34,13 34,13.7 Q5.3
  Top 1.5: 33.27,12.27 34,13
N$2
  Top 0.406: Q5.1 R2.2
N$3
  Top 0.406: JP7.17 37.68,14.68 38,15 38,15.8 R2.1
N$4
  Top 0.5: R18.1 41.84,38.66 U1.5
N$5
  Top 0.4: R17.2 38.45,70.55 39,70 45.7,70 D12.A
  Top 0.5: 1LODRV.3 1LODRV.2
  Top 0.6: R17.2 37.59,70.64 1LODRV.3
N$6
  Top 0.406: 81.95,94.25 R3.2
  Top 1: TRAFO.1 81.95,94.25
N$7
  Top 0.406: 91.15,94.3 C9.1
  Top 1: TRAFO.2 91.15,94.3
N$8
  Top 0.406: R11.2 94.2,90.15 R6.2
N$9
  Top 0.5: IC1.3 33.08,58.37 R19.1
  Top 0.6: R21.1 38,52.9 38,51 33,51 32.9,51.1 R22.2 32.9,58.35 R19.1
N$10
  Top 0.406: R8.2 84.8,80.1 R13.1 D3.A
N$11  (1 unrouted)
N$12
  Top 0.5: U1.7 40.4,34.7 37.2,31.3 37.79,30.81 2HDRV.2 2HDRV.3
N$13
  Top 0.5: 36.84,95.16 1HDRV.3 | 36.84,95.16 1HDRV.2 | U2.7 39.4,88.91 39.4,92.6 36.84,95.16 | 36.84,95.16
N$15
  Top 0.5: C17.1 R20.2 34.3,59.9 34.6,59.6 36.33,59.6 IC1.2 36.44,59.6 38.3,59.6 38.9,59 39,59 39,58 39.91,57.09 IC1.5
N$16
  Top 0.5: 36,44.2 38.04,44.2 R18.2
  Top 0.6: 36,44 D11.A | 36,44 35.6,44.4 2LODRV.3 | 36,44 36,44.2 35.9,43.97 2LODRV.2
N$17
  Top 0.406: R26.2 R25.2
  Top 0.5: U$1.1 45.2,20 44.4,20.8 43.1,20.8 R26.2
N$18
  Top 0.5: IC1.6 43.64,58.37 44,58 46,58 R24.1 R23.2
N$20
  Top 0.5: 30.6,34 D1.C
  Top 1: D5.K 30.6,34
N$23
  Top 0.5: R27.1 R9.2
N$24
  Top 0.5: D6.C 46.6,97.9 D7.K
N$29
  Top 0.406: 26,5.46 26.66,4.8 R10.2 38.7,5.1 R29.2
  Top 0.5: 23,6 R28.1 23.79,5.46
  Top 1.5: 23.79,5.46 26,5.46 R12.E
N$30
  Top 0.5: R9.1 20,8 21,9 22.55,9 R28.2 23,10 24.36,10.5
  Top 1.5: 24.36,10.5 R12.A
N$31
  Top 0.406: R7.2 29,7 28,8 R12.S
O_IFB  (via drill 0.51 pad 1.5)
  Top 0.254: 78.3,14 JP7.1
  Top 0.406: R24.2 45.1,61.1 43.9,59.7 41.67,59.7 IC1.7
  Top 1: v48,61 R24.2
  Top 1.5: v78.3,16 78.3,14
  Bottom 0.5: v78.3,16 74.3,20 59,20 57,22 57,41 48,50 v48,61
PUMP+
  Top 0.254: P+2.1 91,73 91.38,73.27
  Top 0.406: P+1.1 94,75 95,76 95,83 94.65,84.35 R11.1 90.4,85.35 TRAFO.3
  Bottom 0.5: C1.+ 96,109 97,108 97,102 98,101 98,74 96,72 P+2.1
  pour Top (isolate 2, rank 2): 95,86 95,73 91,73 91,77 94,77 94,84.6 90,84.6 90,86
  pour Bottom (isolate 2, rank 3): -16,24 -16,8 7,8 7,14 24,14 27,16 27,103 40,103 40,113 44,113 45,112 45,109 50,109 50,112 64,112 64,108 65,107 70,107 70,112 86,112 89,109 89,107 105,107 105,121 16,121 13,111 6,111 6,118 -17,118 -17,102 5,102 5,107 14,107 19,112 29,112 29,108 22,108 20,105 20,21 18,19 6,19 6,24
  pour Top (isolate 2, rank 4): 3,24 3,8 7,8 7,14 24,14 26,16 27,103 39,103 39,113 44,113 45,112 45,109 50,109 50,112 64,112 64,108 65,107 70,107 70,112 86,112 89,109 89,107 99,107 99,121 32,121 32,111 6,111 6,118 1,118 1,102 6,102 6,108 23,108 23,21 18,17 6,17 6,24
RED  (via drill 2.2 pad 3.81)  (2 unrouted)
  other vias: 12,30
  pour Bottom (isolate 2, rank 4): 2,48 13,48 13,45 8,45 6,43 6,34 18,34 18,24 11,20 10,20 9,21 2,27
  pour Top (isolate 2): 10,23 11,35 18,34 18,24 19,24 17,22 15,22 14,21 10,21
  pour Top (isolate 2, rank 3): 1,63 13,63 13,60 7,60 7,48 13,48 13,45 8,45 6,43 6,35 12,35 12,21 11,20 10,20 9,21 9,27 1,28
SCR2
  pour Top (isolate 2): 95,53 95,50 81,50 81,53
  pour Bottom (isolate 2): 95,53 95,50 81,50 81,53
SNUB1
  pour Top (isolate 2, rank 2): 79,53 79,41 72,41 72,53
  pour Bottom (isolate 2, rank 2): 79,53 79,41 72,41 72,53
SNUB2
  pour Top (isolate 2, rank 2): 79,37 79,25 72,25 72,37
  pour Bottom (isolate 2, rank 2): 79,37 79,25 72,25 72,37
SOURCE
  pour Top (isolate 2): 95,37 95,34 81,34 81,37
  pour Bottom (isolate 2): 95,37 95,34 81,34 81,37
TFB
  Top 0.406: C2.1 39.68,18.85 NTC.1 40.63,15.03 40.2,14.4 | JP7.16 40.2,13.22
  Top 1.5: 40.2,13.22 40.2,14.4
V12  (via drill 0.6 pad 1.27, 0.6 pad 1.5)
  Top 0.254: 40,53 R21.2 | V12_2.1 82,72 82,73 82.17,73
  Top 0.406: C7.+ 88.45,77.45 87,76 84,76 V12_1.1 | V12_1.1 R13.2 | D9.K 80,78 V12_1.1 | JP7.12 50.2,13.18 | VENT.2 30.73,12.27
  Top 0.5: 2LODRV.8 30.4,41.6 31,41 | 2LODRV.1 34.5,41 | 1LODRV.8 30.4,67.6 31,67 | 34.5,67 34.75,67.25 1LODRV.1 | 50.3,12.92 JP7.12 | U2.1 35.14,82.46 D10.A C14.1 34.55,81 v33,81
  Top 0.6: 1LODRV.1 35.69,68 | D8.A 48.4,31.5 U1.1 | v42,41 C16.1 | 36.69,41 2LODRV.1 | 41.69,61.7 IC1.8
  Top 1: v42,41 36.69,41 | v42,62.7 41.69,61.7 | v42,53 40,53 | v72,67 83,67 V12_2.1 | 34.5,41 31,41 | 34.5,67 31,67 | 34.75,67.25 35,67 v42,67 41,68 C15.1 | v50.3,10.5 50.3,12.92 | 50.55,18.4 50.55,17.85 50.5,17.8 50.5,16.26 IC3.3
  Top 1.016: 52.75,30.6 C13.1
  Top 1.5: 52.75,30.6 v50.8,30.6 50.3,31.1 D8.A | C8.+ 50.55,18.4 U$1.3 | IC3.3 50.34,13.04 JP7.12 | 30.73,12.27 v30.2,13.8
  Bottom 0.406: v30.2,13.8 30,14 | 47,31 50.4,31 v50.8,30.6
  Bottom 0.5: 50,17 50.1,17 50.3,16.8 | 50,30.5 49.68,30.6 50,30.6 v50.8,30.6
  Bottom 1: 30,14 47,31
  Bottom 1.5: v42,67 v42,62.7 v42,53 v42,41 42,38.6 50,30.6 | v33,81 42,72 v42,67 | v42,67 v72,67 | 50.3,16.8 v50.3,10.5 | 50,30.5 50,17
  pour Top (isolate 2): 89,79 89,73 80,73 80,78 87,78
VB1
  Top 0.406: D10.K 35,89 38.27,89 U2.8
  Top 0.5: 1HDRV.8 31,96.68 31,96 34,93 34,92 35.49,93.49 1HDRV.1
  pour Top (isolate 1.5, rank 2): 32,98 42,98 42,95 39,92 39,87 38,88 34,88 31,96
VB2
  Top 0.5: 2HDRV.8 35.82,25 36,25 33.95,22.95 C12.1 | 2HDRV.1 39.18,29 40,29 41,30 | 41,30 42,31 41.99,31.01 U1.8 | D8.K 42.4,31 41,30
  pour Top (isolate 1.5): 33,23 34,22 36,23 43,30 43,33 42,33 33,24
VDD
  Top 0.5: IC3.1 45.26,17.56 45.5,17.8 46.4,17.8 46.7,18.1 | U$1.4 47.5,23.5 47.9,23.1
  Top 1: R26.1 47.9,23.1 48,23 48,21.6 47.6,21.2 47.6,19 46.7,18.1
  Top 1.5: JP7.14 45.3,16.06 IC3.1
  pour Top (isolate 0.8): 45,25 53,25 53,24 51,20 49,20 49,19 46,15 44,15 43,23
VFB
  Top 0.406: R7.1 36,7 38,9 42,9 42.8,10 43.5,9.5 C10.1 | 42.8,12.76 JP7.15
  Top 1.5: 42.8,10 42.8,12.76
VS3
  Top 0.5: D1.A 25.3,31.51 ROUT6.1 | U1.6 39.06,36 38.1,35 37.4,34.4 36,34 36,33.19 2HDRV.4 35.18,33 35,33 | 32,28.82 2HDRV.5 | 32,28.82 32,29 | 32,28.82 31.82,29 31,29 29.45,27.45 C12.2
  pour Top (isolate 1.5): 25,32 26,32 29,29 30,29 36,35 42,35 42,34 38,34 31,27 28,26 25,29
VS4
  Top 0.5: 1HDRV.5 35.32,101 38,99 39,98 39,97 38.51,96.51 1HDRV.4 | U2.6 40.8,88.84 40.8,90.3 41.8,91.3 41.8,91.4
  pour Top (isolate 1.5): 25,108 29,108 39,98 43.9,97.8 44,93.6 41,88 40,95 34,101 33,101 29,105 26,105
